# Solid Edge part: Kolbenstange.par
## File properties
Username: bmolnar
Dokumentum tartalom típus: 0
Author: bmolnar
Last saved by: bmolnar
Revision: 78
Sűrűség: 0,000 kg/m^3
Pontosság: 0,990
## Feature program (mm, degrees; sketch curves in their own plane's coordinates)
base feature "unnamed BaseFeature 1"
sketch for "unnamed Protrusion 1" plane through (18.4, 0, 0) normal (1, 0, 0) x-axis (0, 1, 0)
  circle centre (0, 0) radius 8
extrude "unnamed Protrusion 1" add finite 19.7 along +normal
sketch for "Kihúzás_2" #1 plane through (18.4, 0, 0) normal (1, 0, 0) x-axis (0, 1, 0)
  circle centre (0, 0) radius 4
sketch for "Kihúzás_2" #2 plane through (18.4, 0, 0) normal (1, 0, 0) x-axis (0, 1, 0)
  circle centre (0, 0) radius 8
extrude "Kihúzás_2" add finite 5.5 along -normal
sketch for "Furat_1" plane through (-3, 0, 0.0012) normal (-1, 0, 0) x-axis (0, 0, 1)
  hole centre (-0.0012, 0) bore radius 1.621
hole "Furat_1" nominal diameter 4 finite  VBottomAngle = 118 deg; ThreadDepth = 9 mm
chamfer "Letörés_1" setback 0.2  SetBackValue2 = 45 deg
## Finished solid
Body 1: solid body, 18 faces, 24 edges, 8 vertices.
  Faces by surface: plane 8, cylinder 5, cone 3, torus 2
  Edges by curve: circle 14, line 6, curve on surface 2, ellipse 2
Bounding box of the edges (mm; curved faces can reach further): 43.100 x 16.000 x 16.000, from (-5, -8, -8) to (38.1, 8, 8).
Cylindrical faces by radius (mm): R1.621 x2, R2.125 x1, R4 x1, R8 x1
Conical faces (half-angle, radius in mm at the cone's reference point): 45 deg R1.821 x1, 45 deg R2.225 x1, 59 deg R1.621 x1
Toroidal faces (ring radius, tube radius in mm): R1.925 r0.2 x1, R2.7 r1.3 x1
Planar faces by outward normal: +x 1, +z 1, -x 3, -z 1, oblique 2
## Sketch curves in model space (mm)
circle centre (18.4, 0, 0) radius 8
circle centre (18.4, 0, 0) radius 4
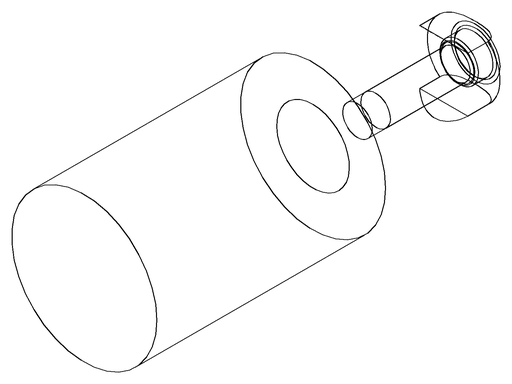
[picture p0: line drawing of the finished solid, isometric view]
